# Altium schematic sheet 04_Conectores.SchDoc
size A; SheetNumber: 4; SheetTotal: 4
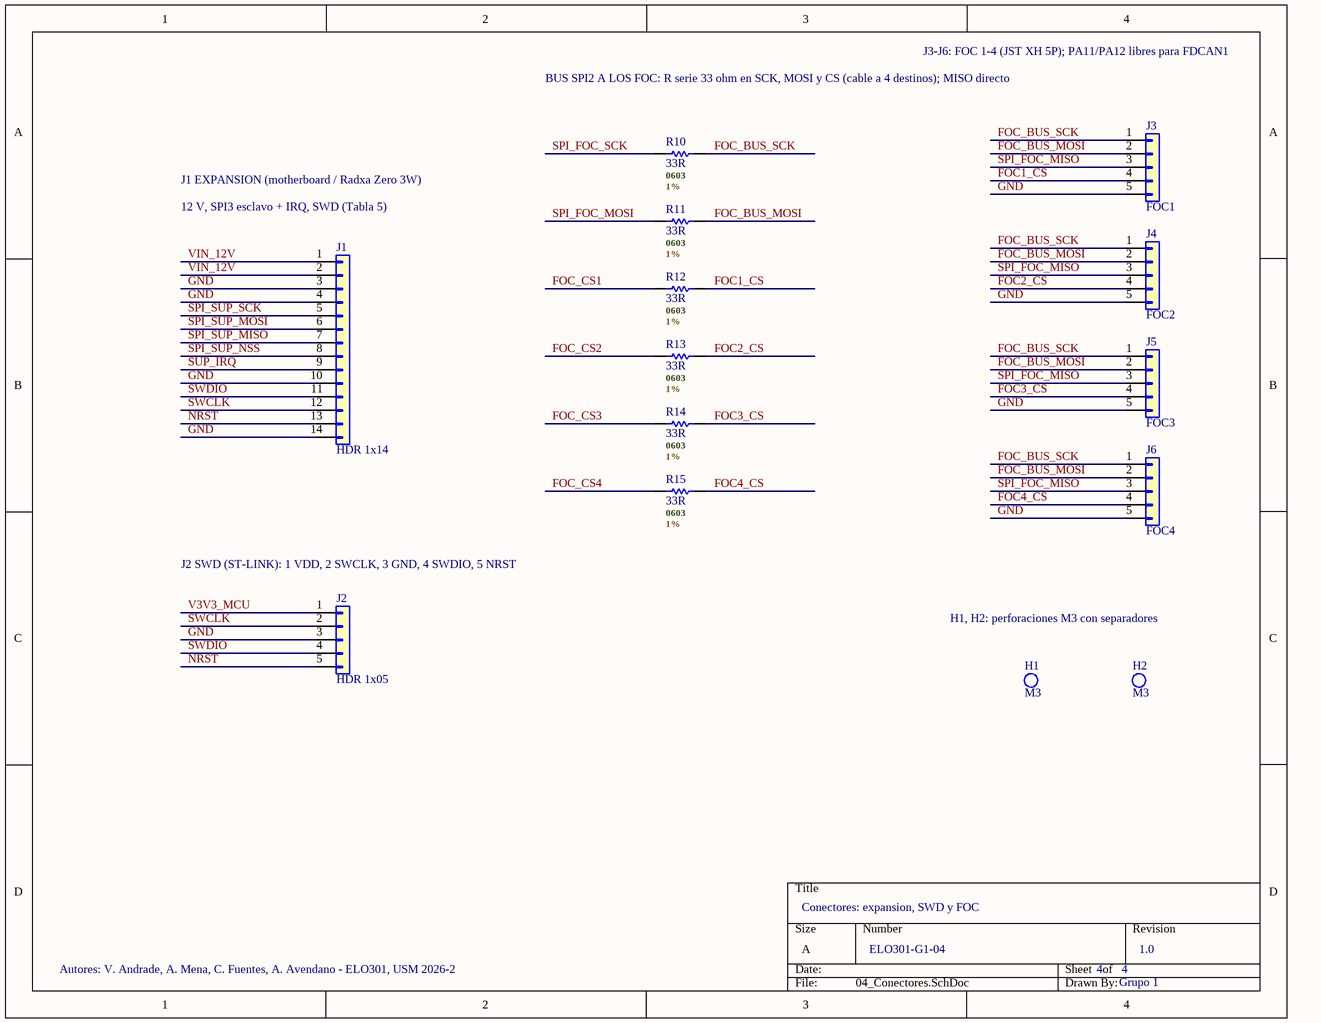
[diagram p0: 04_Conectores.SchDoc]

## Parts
H1  M3  [M3 - HOLE]
H2  M3  [M3 - HOLE]
J1  HDR 1x14  [HDR 1x14 2.54 - BOOMELE]
J2  HDR 1x05  [HDR 1x05 2.54 - BOOMELE]
J3  FOC1  [B5B-XH-A - JST]
J4  FOC2  [B5B-XH-A - JST]
J5  FOC3  [B5B-XH-A - JST]
J6  FOC4  [B5B-XH-A - JST]
R10  33R  .Case/Package: 0603  .Tolerance: 1%  [R0603 - YAGEO]
R11  33R  .Case/Package: 0603  .Tolerance: 1%  [R0603 - YAGEO]
R12  33R  .Case/Package: 0603  .Tolerance: 1%  [R0603 - YAGEO]
R13  33R  .Case/Package: 0603  .Tolerance: 1%  [R0603 - YAGEO]
R14  33R  .Case/Package: 0603  .Tolerance: 1%  [R0603 - YAGEO]
R15  33R  .Case/Package: 0603  .Tolerance: 1%  [R0603 - YAGEO]

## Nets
FOC1_CS: J3.4(Pin_4) R12.2
FOC2_CS: J4.4(Pin_4) R13.2
FOC3_CS: J5.4(Pin_4) R14.2
FOC4_CS: J6.4(Pin_4) R15.2
FOC_BUS_MOSI: J3.2(Pin_2) J4.2(Pin_2) J5.2(Pin_2) J6.2(Pin_2) R11.2
FOC_BUS_SCK: J3.1(Pin_1) J4.1(Pin_1) J5.1(Pin_1) J6.1(Pin_1) R10.2
FOC_CS1: R12.1
FOC_CS2: R13.1
FOC_CS3: R14.1
FOC_CS4: R15.1
GND: J1.3(Pin_3) J1.4(Pin_4) J1.10(Pin_10) J1.14(Pin_14) J2.3(Pin_3) J3.5(Pin_5) J4.5(Pin_5) J5.5(Pin_5) J6.5(Pin_5)
NRST: J1.13(Pin_13) J2.5(Pin_5)
SPI_FOC_MISO: J3.3(Pin_3) J4.3(Pin_3) J5.3(Pin_3) J6.3(Pin_3)
SPI_FOC_MOSI: R11.1
SPI_FOC_SCK: R10.1
SPI_SUP_MISO: J1.7(Pin_7)
SPI_SUP_MOSI: J1.6(Pin_6)
SPI_SUP_NSS: J1.8(Pin_8)
SPI_SUP_SCK: J1.5(Pin_5)
SUP_IRQ: J1.9(Pin_9)
SWCLK: J1.12(Pin_12) J2.2(Pin_2)
SWDIO: J1.11(Pin_11) J2.4(Pin_4)
V3V3_MCU: J2.1(Pin_1)
VIN_12V: J1.1(Pin_1) J1.2(Pin_2)

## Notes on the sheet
- BUS SPI2 A LOS FOC: R serie 33 ohm en SCK, MOSI y CS (cable a 4 destinos); MISO directo
- J3-J6: FOC 1-4 (JST XH 5P); PA11/PA12 libres para FDCAN1
- J1 EXPANSION (motherboard / Radxa Zero 3W)
- (near J1) 12 V, SPI3 esclavo + IRQ, SWD (Tabla 5)
- (near J2) J2 SWD (ST-LINK): 1 VDD, 2 SWCLK, 3 GND, 4 SWDIO, 5 NRST
- H1, H2: perforaciones M3 con separadores
- Conectores: expansion, SWD y FOC
- Autores: V. Andrade, A. Mena, C. Fuentes, A. Avendano - ELO301, USM 2026-2
- ELO301-G1-04
- 4
- 1.0
- Grupo 1

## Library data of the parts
H1 H2 = MOUNTING HOLE - M3: Mounting Hole without connection
J1 = CONN - 1x14: Generic connector, single row, 01x14, script generated (kicad-library-utils/schlib/autogen/connector/); Manufacturer: BOOMELE; Manufacturer Part Number: 2.54-1*40P (1x14)
J2 = CONN - 1x05: Generic connector, single row, 01x05, script generated (kicad-library-utils/schlib/autogen/connector/); Manufacturer: BOOMELE; Manufacturer Part Number: 2.54-1*40P (1x5)
J3-J6 = CONN - 1x05: Generic connector, single row, 01x05, script generated (kicad-library-utils/schlib/autogen/connector/); Manufacturer: JST; Manufacturer Part Number: B5B-XH-A(LF)(SN)
R10-R15 = RESISTOR - GENERIC: Manufacturer: Yageo; Manufacturer Part Number: RC0603FR-0733RL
